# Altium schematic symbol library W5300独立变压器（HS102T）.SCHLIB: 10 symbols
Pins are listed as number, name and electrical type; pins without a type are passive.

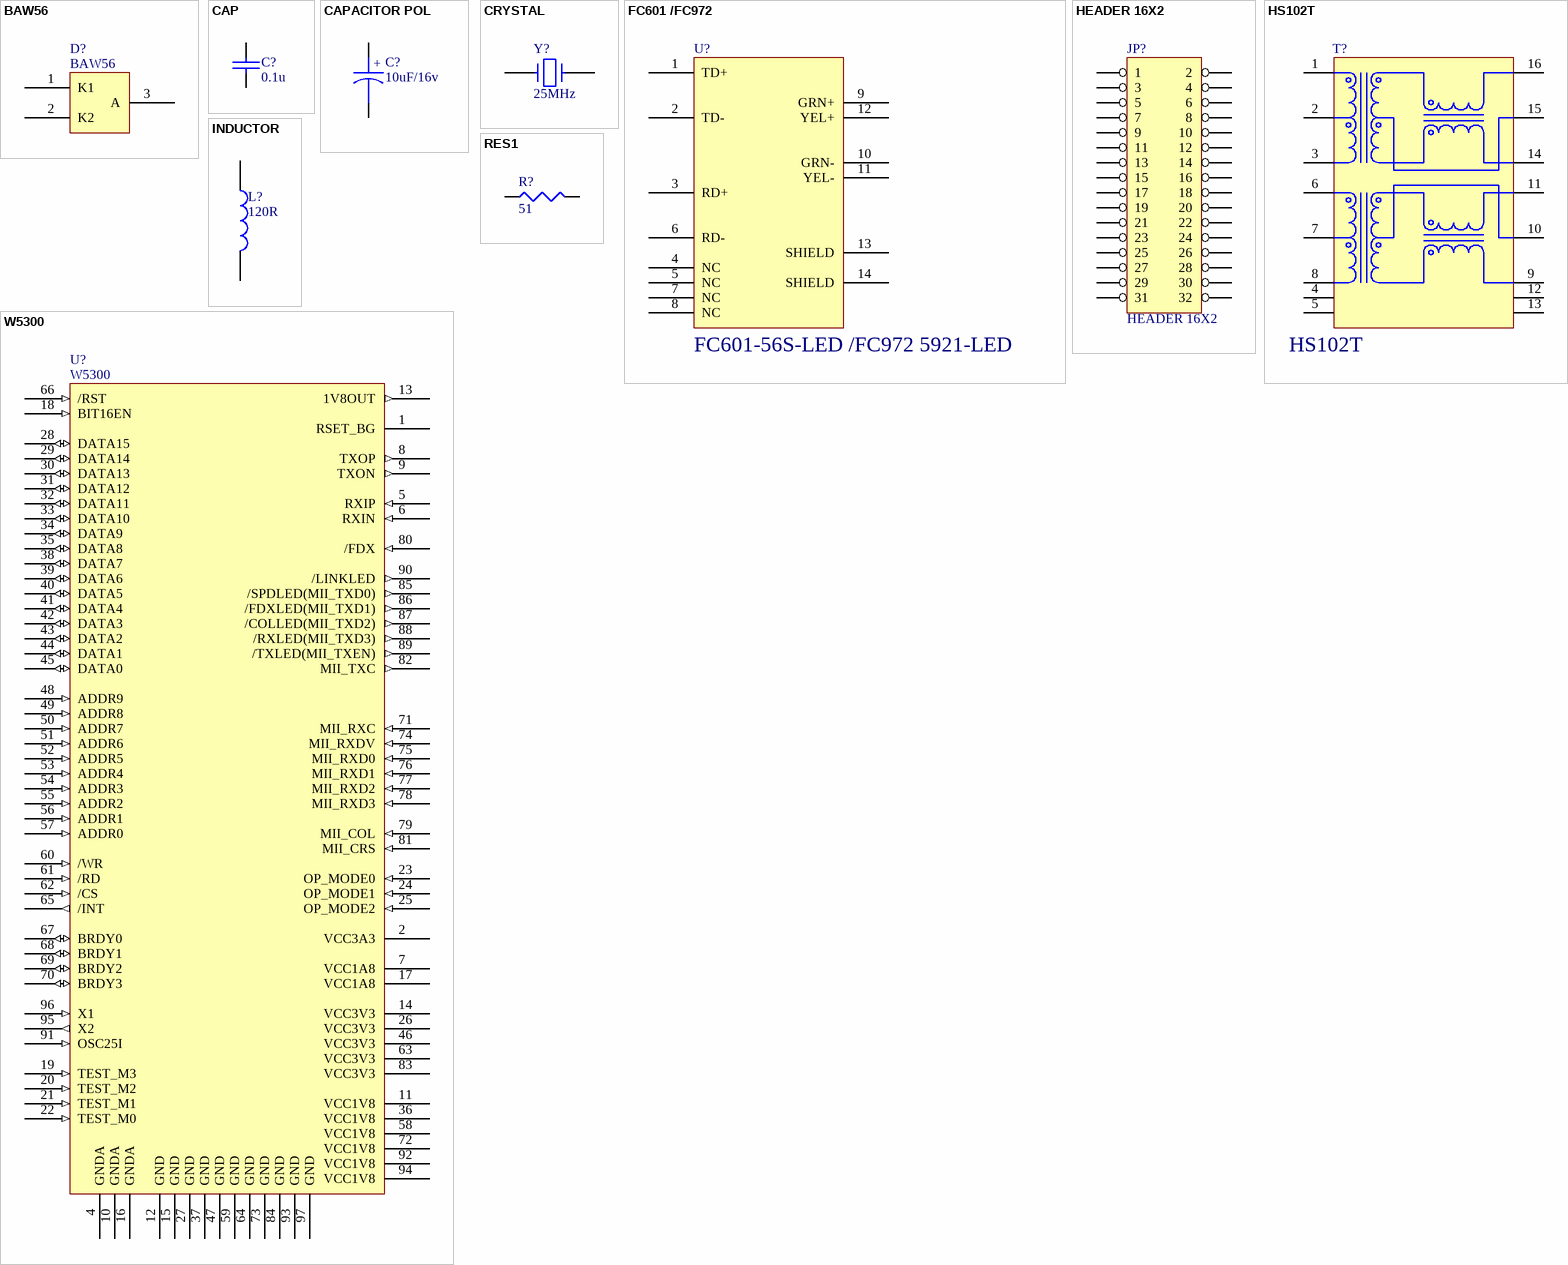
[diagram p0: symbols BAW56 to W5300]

## BAW56
designator D?
footprint SOT-23
pins: 1 K1, 2 K2, 3 A

## CAP
designator C?, comment 0.1u
Capacitor
footprint 0603
pins: 1, 2

## CAPACITOR POL
designator C?, comment 10uF/16v
Capacitor
footprint 3216
pins: 1, 2

## CRYSTAL
designator Y?, comment 25MHz
Crystal
footprint XTAL
pins: 1, 2

## FC601 /FC972
designator U?, comment FC601-56S-LED /FC972 5921-LED
FC601 /FC972
footprint RJ45-5
pins: 1 TD+, 2 TD-, 3 RD+, 4 NC, 5 NC, 6 RD-, 7 NC, 8 NC, 9 GRN+, 10 GRN-, 11 YEL-, 12 YEL+, 13 SHIELD, 14 SHIELD

## HEADER 16X2
designator JP?
footprint IDC32-2
pins: 1, 2, 3, 4, 5, 6, 7, 8, 9, 10, 11, 12, 13, 14, 15, 16, 17, 18, 19, 20, 21, 22, 23, 24, 25, 26, 27, 28, 29, 30, 31, 32

## HS102T
designator T?
版本号: R1.00; 日期: 2008年10月25日; 发行商: VRong LTD.; 赋值: USB
footprint TR-HS101T/HS102T/HS680T
3D model RJ45-1 (PCB3D Model)
simulation model Model Name (Model Description)
signal-integrity model Model Name (Model Description)
pins: 1 TD+, 2 CT, 3 TD-, 4, 5, 6 RD+, 7 CT, 8 RD-, 9 RX-, 10 CT, 11 RX+, 12, 13, 14 TX-, 15 CT, 16 TX+

## INDUCTOR
designator L?, comment 120R
footprint 0603
pins: 1, 2

## RES1
designator R?, comment 51
footprint 0603
pins: 1, 2

## W5300
designator U?
W5100
footprint LQFP100-W5300/VCT6
pins: 1 RSET_BG, 2 VCC3A3 (power), 4 GNDA (power), 5 RXIP (in), 6 RXIN (in), 7 VCC1A8 (power), 8 TXOP (out), 9 TXON (out), 10 GNDA (power), 11 VCC1V8 (power), 12 GND (power), 13 1V8OUT (out), 14 VCC3V3 (power), 15 GND (power), 16 GNDA (power), 17 VCC1A8 (power), 18 BIT16EN (in), 19 TEST_M3 (in), 20 TEST_M2 (in), 21 TEST_M1 (in), 22 TEST_M0 (in), 23 OP_MODE0 (in), 24 OP_MODE1 (in), 25 OP_MODE2 (in), 26 VCC3V3 (power), 27 GND (power), 28 DATA15 (io), 29 DATA14 (io), 30 DATA13 (io), 31 DATA12 (io), 32 DATA11 (io), 33 DATA10 (io), 34 DATA9 (io), 35 DATA8 (io), 36 VCC1V8 (power), 37 GND (power), 38 DATA7 (io), 39 DATA6 (io), 40 DATA5 (io), 41 DATA4 (io), 42 DATA3 (io), 43 DATA2 (io), 44 DATA1 (io), 45 DATA0 (io), 46 VCC3V3 (power), 47 GND (power), 48 ADDR9 (in), 49 ADDR8 (in), 50 ADDR7 (in), 51 ADDR6 (in), 52 ADDR5 (in), 53 ADDR4 (in), 54 ADDR3 (in), 55 ADDR2 (in), 56 ADDR1 (in), 57 ADDR0 (in), 58 VCC1V8 (power), 59 GND (power), 60 /WR (in), 61 /RD (in), 62 /CS (in), 63 VCC3V3 (power), 64 GND (power), 65 /INT (out), 66 /RST (in), 67 BRDY0 (io), 68 BRDY1 (io), 69 BRDY2 (io), 70 BRDY3 (io), 71 MII_RXC (in), 72 VCC1V8 (power), 73 GND (power), 74 MII_RXDV (in), 75 MII_RXD0 (in), 76 MII_RXD1 (in), 77 MII_RXD2 (in), 78 MII_RXD3 (in), 79 MII_COL (in), 80 /FDX (in), 81 MII_CRS (in), 82 MII_TXC (out), 83 VCC3V3 (power), 84 GND (power), 85 /SPDLED(MII_TXD0) (out), 86 /FDXLED(MII_TXD1) (out), 87 /COLLED(MII_TXD2) (out), 88 /RXLED(MII_TXD3) (out), 89 /TXLED(MII_TXEN) (out), 90 /LINKLED (out), 91 OSC25I (in), 92 VCC1V8 (power), 93 GND (power), 94 VCC1V8 (power), 95 X2 (out), 96 X1 (in), 97 GND (power)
